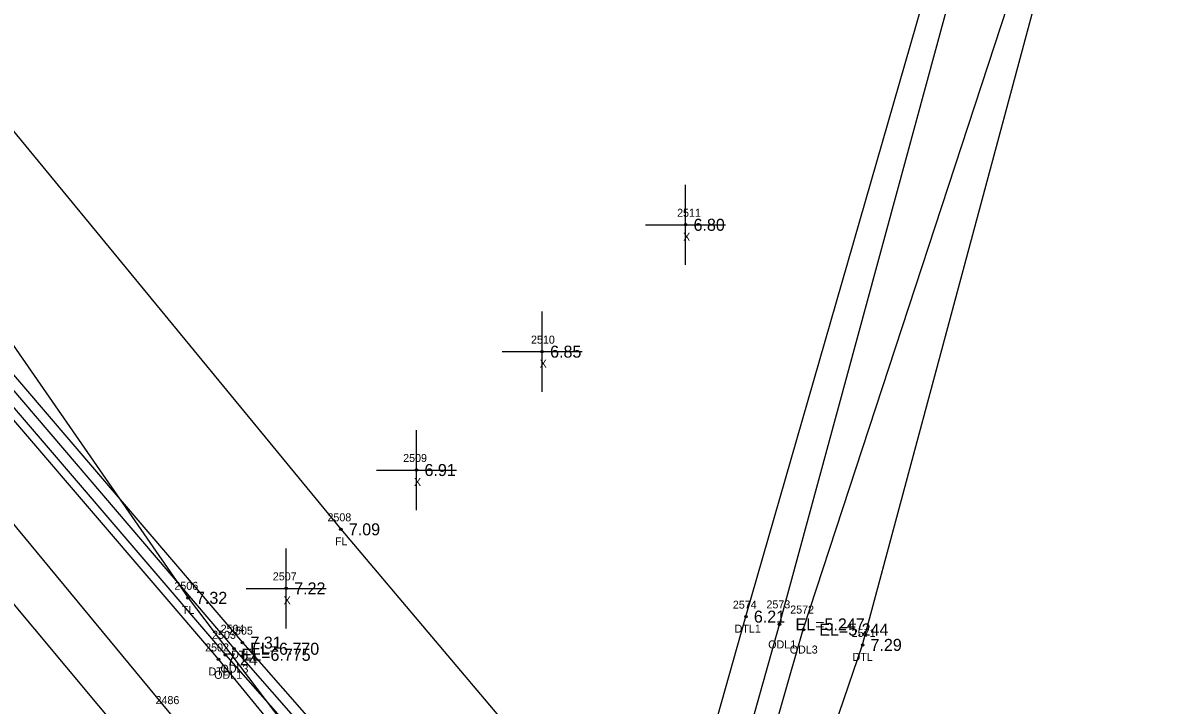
# Model space of a CAD drawing. Extents: x 2042211 to 2045853, y 303080 to 309569.
# Drawn here: x 2044641.9 to 2044785, y 304508.5 to 304593.7 of the extents above; entities that cross this region are included whole.
import ezdxf

# ---------------------------------------------------------------- set-up
doc = ezdxf.new("R2010")
doc.units = 0
for name, color, linetype in [('BR_500YR_SCOUR', 7, 'Continuous'), ('RD_DTM_BkLn1', 7, 'Continuous'), ('RD_DTM_BkLn_txCode', 7, 'Continuous'), ('RD_EX_Fence_Other_txCode', 7, 'Continuous'), ('RD_EX_H2O', 7, 'Continuous'), ('RD_EX_H2O_txCode', 7, 'Continuous'), ('RD_EX_Misc', 7, 'Continuous'), ('RD_EX_Misc_txCode', 7, 'Continuous'), ('RD_EX_Road', 7, 'Continuous'), ('RD_EX_TX_Fence_Other_ELEV', 7, 'Continuous'), ('RD_EX_TX_H2O_ELEV', 7, 'Continuous'), ('RD_EX_TX_Misc_ELEV', 7, 'Continuous'), ('RD_EX_TX_VEG_ELEV', 7, 'Continuous'), ('RD_EX_VEG_txCode', 7, 'Continuous'), ('RD_SMD_Locator', 7, 'Continuous')]:
    doc.layers.add(name, color=color, linetype=linetype)

msp = doc.modelspace()

# ---------------------------------------------------------------- linework, layer by layer
at = {"layer": 'BR_500YR_SCOUR'}
for points in [[(2044387.58, 304996.88), (2044390.53, 304961.86), (2044388.93, 304944.71), (2044397.82, 304931.38), (2044395.87, 304907.56), (2044407.42, 304883.17), (2044412.64, 304877.39), (2044413.34, 304846.91), (2044417.62, 304826.21), (2044417.53, 304827.99), (2044425.41, 304820.87), (2044430.68, 304811.06), (2044486.4, 304757.95), (2044546.53, 304677.07), (2044611.02, 304596.16), (2044662.5, 304521.9), (2044713.91, 304454.08), (2044725.96, 304441.86), (2044733.75, 304433.55)], [(2044487.63, 304762.15), (2044554.33, 304682.4), (2044620.57, 304604.64), (2044681.6, 304530.46), (2044725.33, 304478.72)]]:
    msp.add_lwpolyline(points, dxfattribs=at)
msp.add_circle((2044662.5, 304521.9), 0.15, dxfattribs=at)
at = {"layer": 'RD_DTM_BkLn1'}
msp.add_lwpolyline([(2044398.41, 304821.04), (2044402.86, 304816.02), (2044414.62, 304801.81), (2044465.4, 304737.7), (2044530.97, 304661.39), (2044596.61, 304584.37), (2044660.09, 304507.62), (2044710.08, 304447.81), (2044714.26, 304444.21), (2044718.28, 304439), (2044721.7, 304430.82), (2044787.25, 304353.1)], dxfattribs=at)
at = {"layer": 'RD_EX_H2O'}
for points in [[(2044415.25, 304826.5), (2044425.66, 304808.25), (2044476.98, 304747.65), (2044539.62, 304670.39), (2044605.13, 304591.24), (2044669.3, 304516.3), (2044710.53, 304469.32), (2044713.85, 304468.76), (2044716.6, 304472.63), (2044721.53, 304481.66), (2044732.23, 304519.55), (2044759.21, 304613.29), (2044789.62, 304712.59), (2044819.6, 304810.16), (2044847.46, 304908.11)], [(2044716.81, 304455.02), (2044724.41, 304475.71), (2044736.43, 304518.58), (2044762.06, 304612.81), (2044791.72, 304711.72), (2044823.39, 304808.82), (2044851.52, 304906.14)], [(2044719.06, 304454.51), (2044726.58, 304473.3), (2044739.4, 304517.94), (2044769.91, 304611.11), (2044797.28, 304709.9), (2044827.72, 304807.52), (2044855.71, 304905.79)], [(2044719.89, 304440.12), (2044724.28, 304439.56), (2044726.76, 304444.25), (2044726.49, 304449.96), (2044727.04, 304454.87), (2044730.56, 304468.48), (2044746.81, 304516.02), (2044772.02, 304609.79), (2044801.76, 304708.94), (2044831.05, 304807.04), (2044857.93, 304905.05)], [(2044412.68, 304824.61), (2044424.35, 304807.8), (2044474.04, 304744.84), (2044537.22, 304668.23), (2044604.12, 304590.58), (2044668.25, 304515.54), (2044711.53, 304466.18), (2044714.74, 304463.76), (2044717.49, 304460.61)], [(2044410.56, 304822.99), (2044421.91, 304806.08), (2044470.67, 304741.87), (2044535.46, 304666.28), (2044602.12, 304589.07), (2044666.31, 304514.2), (2044707.72, 304463.54), (2044711.05, 304453.94), (2044714.6, 304446.34)], [(2044411.61, 304823.92), (2044423.39, 304807.22), (2044471.39, 304742.74), (2044536.14, 304667.19), (2044602.88, 304589.74), (2044667.18, 304514.78), (2044710.55, 304465.6), (2044713.57, 304459.34), (2044715.66, 304454.88)]]:
    msp.add_lwpolyline(points, dxfattribs=at)
at = {"layer": 'RD_EX_Misc'}
for p, q in [((2044724.69, 304563.51), (2044724.69, 304573.51)), ((2044719.69, 304568.51), (2044729.69, 304568.51)), ((2044706.76, 304547.66), (2044706.76, 304557.66)), ((2044701.76, 304552.66), (2044711.76, 304552.66)), ((2044691.06, 304532.87), (2044691.06, 304542.87)), ((2044686.06, 304537.87), (2044696.06, 304537.87)), ((2044674.77, 304518.08), (2044674.77, 304528.08)), ((2044669.77, 304523.08), (2044679.77, 304523.08))]:
    msp.add_line(p, q, dxfattribs=at)
at = {"layer": 'RD_EX_Road'}
msp.add_lwpolyline([(2044013.41, 305270.34), (2044077.97, 305194.15), (2044141.4, 305117.67), (2044205.92, 305040.83), (2044269.54, 304964.65), (2044331.73, 304891.04), (2044335.22, 304889.2), (2044346.01, 304875.31), (2044356.18, 304867.61), (2044370.01, 304868.14), (2044386.83, 304866.36), (2044389.44, 304849.53), (2044390.71, 304830.73), (2044393.77, 304818.44), (2044395.5, 304814.18), (2044398.16, 304811.09), (2044461.8, 304734.03), (2044526.04, 304657.6), (2044591.28, 304580.23), (2044655.29, 304503.62), (2044718.26, 304427.32), (2044783.13, 304349.86)], dxfattribs=at)
at = {"layer": 'RD_SMD_Locator'}
for centre in [(2044724.69, 304568.51), (2044706.76, 304552.66), (2044691.06, 304537.87), (2044681.6, 304530.46), (2044674.77, 304523.08), (2044732.23, 304519.55), (2044736.43, 304518.58), (2044739.4, 304517.94), (2044669.3, 304516.3), (2044668.25, 304515.54), (2044746.81, 304516.02), (2044666.31, 304514.2), (2044667.18, 304514.78)]:
    msp.add_circle(centre, 0.15, dxfattribs=at)

# ---------------------------------------------------------------- texts
at = {"layer": 'RD_DTM_BkLn_txCode'}
msp.add_text('2486', height=1, dxfattribs=at).set_placement((2044658.44, 304508.62))
at = {"layer": 'RD_EX_Fence_Other_txCode'}
for s, p in [('2508', (2044679.93, 304531.46)), ('FL', (2044680.87, 304528.46))]:
    msp.add_text(s, height=1, dxfattribs=at).set_placement(p)
at = {"layer": 'RD_EX_H2O_txCode'}
for s, p in [('2574', (2044730.6, 304520.55)), ('2573', (2044734.8, 304520.58)), ('2572', (2044737.77, 304519.94)), ('2504', (2044666.58, 304517.54)), ('2505', (2044667.63, 304517.3)), ('DTL1', (2044730.82, 304517.55)), ('2571', (2044745.46, 304517.02)), ('2503', (2044665.51, 304516.78)), ('ODL1', (2044735.02, 304515.58)), ('2502', (2044664.64, 304515.2)), ('DTL1', (2044667.89, 304514.3)), ('ODL3', (2044737.71, 304514.94)), ('DTL', (2044745.57, 304514.02)), ('ODL3', (2044666.55, 304512.54)), ('DTL', (2044665.07, 304512.2)), ('ODL1', (2044665.77, 304511.78))]:
    msp.add_text(s, height=1, dxfattribs=at).set_placement(p)
at = {"layer": 'RD_EX_Misc_txCode'}
for s, p in [('2511', (2044723.63, 304569.51)), ('X', (2044724.38, 304566.51)), ('2510', (2044705.37, 304553.66)), ('X', (2044706.45, 304550.66)), ('2509', (2044689.39, 304538.87)), ('X', (2044690.74, 304535.87)), ('2507', (2044673.1, 304524.08)), ('X', (2044674.45, 304521.08))]:
    msp.add_text(s, height=1, dxfattribs=at).set_placement(p)
at = {"layer": 'RD_EX_TX_Fence_Other_ELEV'}
msp.add_text('7.09', height=1.5, dxfattribs=at).set_placement((2044682.6, 304529.71))
at = {"layer": 'RD_EX_TX_H2O_ELEV'}
for s, p in [('6.21', (2044733.23, 304518.8)), ('EL=5.247', (2044738.43, 304517.83)), ('EL=5.244', (2044741.4, 304517.19)), ('7.31', (2044670.3, 304515.55)), ('7.29', (2044747.81, 304515.27)), ('7.24', (2044667.31, 304513.45)), ('EL=6.775', (2044669.18, 304514.03)), ('EL=6.770', (2044670.25, 304514.79))]:
    msp.add_text(s, height=1.5, dxfattribs=at).set_placement(p)
at = {"layer": 'RD_EX_TX_Misc_ELEV'}
for s, p in [('6.80', (2044725.69, 304567.76)), ('6.85', (2044707.76, 304551.91)), ('6.91', (2044692.06, 304537.12)), ('7.22', (2044675.77, 304522.33))]:
    msp.add_text(s, height=1.5, dxfattribs=at).set_placement(p)
at = {"layer": 'RD_EX_TX_VEG_ELEV'}
msp.add_text('7.32', height=1.5, dxfattribs=at).set_placement((2044663.5, 304521.15))
at = {"layer": 'RD_EX_VEG_txCode'}
for s, p in [('2506', (2044660.8, 304522.9)), ('TL', (2044661.73, 304519.9))]:
    msp.add_text(s, height=1, dxfattribs=at).set_placement(p)

doc.saveas('drawing.dxf')
